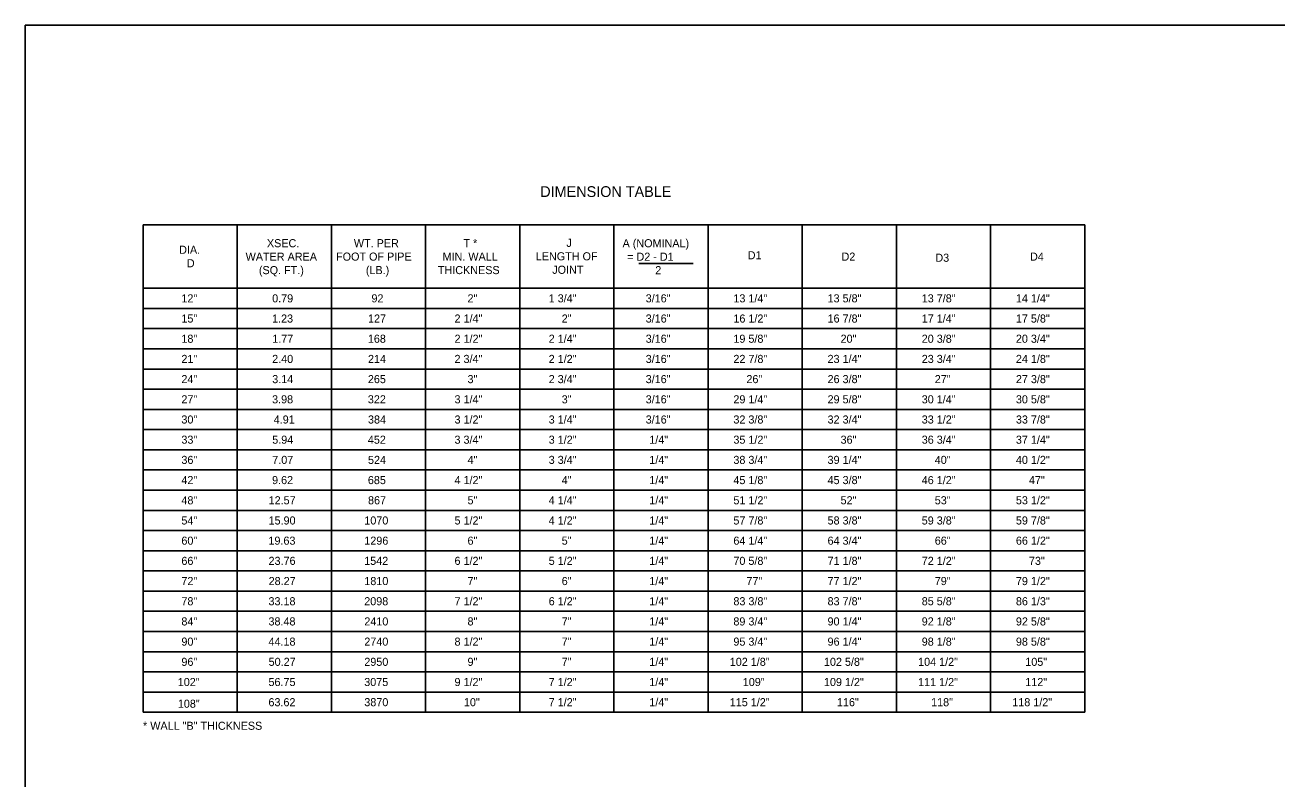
# Model space of a CAD drawing. Extents: x 49991.4 to 50021, y 49987.6 to 50011.4.
# Drawn here: x 49999.38 to 50008.69, y 49993.4 to 49999 of the extents above; entities that cross this region are included whole.
import ezdxf

# ---------------------------------------------------------------- set-up
doc = ezdxf.new("R2010")
doc.units = 0
doc.layers.add('Level 1', color=7, linetype='Continuous')
doc.layers.add('Level 2', color=7, linetype='Continuous')

msp = doc.modelspace()

# ---------------------------------------------------------------- linework, layer by layer
at = {"layer": 'Level 1'}
msp.add_lwpolyline([(49999.3835, 49998.9992), (50016.7501, 49998.9992), (50016.7501, 49987.7988), (49999.3835, 49987.7988)], close=True, dxfattribs=at)
at = {"layer": 'Level 2'}
for p, q in [((50000.2607, 49997.5141), (50000.2607, 49993.8941)), ((50000.2607, 49997.5141), (50007.2607, 49997.5141)), ((50000.9607, 49997.5141), (50000.9607, 49993.8941)), ((50001.6607, 49997.5141), (50001.6607, 49993.8941)), ((50002.3607, 49997.5141), (50002.3607, 49993.8941)), ((50003.0607, 49997.5141), (50003.0607, 49997.0441)), ((50003.7607, 49997.5141), (50003.7607, 49993.8941)), ((50004.4607, 49997.5141), (50004.4607, 49993.8941)), ((50005.1607, 49997.5141), (50005.1607, 49997.0441)), ((50005.8607, 49997.5141), (50005.8607, 49997.0441)), ((50006.5607, 49997.5141), (50006.5607, 49997.0441)), ((50007.2607, 49997.5141), (50007.2607, 49993.8941)), ((50003.945, 49997.2284), (50004.351, 49997.2284)), ((50000.2607, 49997.0441), (50007.2607, 49997.0441)), ((50003.0607, 49997.0428), (50003.0607, 49993.8941)), ((50005.1607, 49997.0441), (50005.1607, 49993.8941)), ((50005.8607, 49997.0441), (50005.8607, 49993.8941)), ((50006.5607, 49997.0402), (50006.5607, 49993.8941)), ((50000.2607, 49996.8941), (50007.2607, 49996.8941)), ((50000.2607, 49996.7441), (50007.2607, 49996.7441)), ((50000.2607, 49996.5941), (50007.2607, 49996.5941)), ((50000.2607, 49996.4441), (50007.2607, 49996.4441)), ((50000.2607, 49996.2941), (50007.2607, 49996.2941)), ((50000.2607, 49996.1441), (50007.2607, 49996.1441)), ((50000.2607, 49995.9941), (50007.2607, 49995.9941)), ((50000.2607, 49995.8441), (50007.2607, 49995.8441)), ((50000.2607, 49995.6941), (50007.2607, 49995.6941)), ((50000.2607, 49995.5441), (50007.2607, 49995.5441)), ((50000.2607, 49995.3941), (50007.2607, 49995.3941)), ((50000.2607, 49995.2441), (50007.2607, 49995.2441)), ((50000.2607, 49995.0941), (50007.2607, 49995.0941)), ((50000.2607, 49994.9441), (50007.2607, 49994.9441)), ((50000.2607, 49994.7941), (50007.2607, 49994.7941)), ((50000.2607, 49994.6441), (50007.2607, 49994.6441)), ((50000.2607, 49994.4941), (50007.2607, 49994.4941)), ((50000.2607, 49994.3441), (50007.2607, 49994.3441)), ((50000.2607, 49994.1941), (50007.2607, 49994.1941)), ((50000.2607, 49994.0441), (50007.2607, 49994.0441)), ((50000.2607, 49993.8941), (50007.2607, 49993.8941))]:
    msp.add_line(p, q, dxfattribs=at)

# ---------------------------------------------------------------- texts
for s, height, p in [('DIMENSION TABLE', 0.08, (50003.2133, 49997.7221)), ('XSEC.', 0.06, (50001.1815, 49997.3487)), ('WT. PER', 0.06, (50001.8278, 49997.3491)), ('T *', 0.06, (50002.6424, 49997.3491)), ('J ', 0.06, (50003.4077, 49997.3514)), (' A (NOMINAL)', 0.06, (50003.8029, 49997.3484)), ('DIA.', 0.06, (50000.529, 49997.2999)), ('WATER AREA', 0.06, (50001.0232, 49997.2487)), ('FOOT OF PIPE', 0.06, (50001.6956, 49997.2491)), ('MIN. WALL', 0.06, (50002.4873, 49997.2491)), ('LENGTH OF', 0.06, (50003.1801, 49997.2514)), ('= D2 - D1', 0.06, (50003.8595, 49997.2484)), ('D1', 0.06, (50004.7555, 49997.2593)), ('D2', 0.06, (50005.4526, 49997.2491)), ('D3', 0.06, (50006.1504, 49997.2407)), ('D4', 0.06, (50006.8538, 49997.2491)), ('D', 0.06, (50000.586, 49997.1999)), ('(SQ. FT.)', 0.06, (50001.1219, 49997.1487)), ('(LB.)', 0.06, (50001.9169, 49997.1491)), ('THICKNESS', 0.06, (50002.4522, 49997.1491)), ('JOINT', 0.06, (50003.3026, 49997.1514)), ('  2 ', 0.06, (50004.0237, 49997.1484)), ('12"', 0.06, (50000.5458, 49996.9391)), ('0.79', 0.06, (50001.2205, 49996.9391)), ('92', 0.06, (50001.9586, 49996.9391)), ('2"', 0.06, (50002.6727, 49996.9391)), ('1 3/4"', 0.06, (50003.276, 49996.9391)), ('3/16"', 0.06, (50003.997, 49996.9391)), ('13 1/4"', 0.06, (50004.649, 49996.9391)), ('13 5/8"', 0.06, (50005.349, 49996.9391)), ('13 7/8"', 0.06, (50006.049, 49996.9391)), ('14 1/4"', 0.06, (50006.749, 49996.9391)), ('15"', 0.06, (50000.5458, 49996.7891)), ('1.23', 0.06, (50001.2198, 49996.7891)), ('127', 0.06, (50001.933, 49996.7891)), ('2 1/4"', 0.06, (50002.5761, 49996.7891)), ('2"', 0.06, (50003.3727, 49996.7891)), ('3/16"', 0.06, (50003.997, 49996.7891)), ('16 1/2"', 0.06, (50004.649, 49996.7891)), ('16 7/8"', 0.06, (50005.349, 49996.7891)), ('17 1/4"', 0.06, (50006.049, 49996.7891)), ('17 5/8"', 0.06, (50006.749, 49996.7891)), ('18"', 0.06, (50000.5458, 49996.6391)), ('1.77', 0.06, (50001.2212, 49996.6391)), ('168', 0.06, (50001.9318, 49996.6391)), ('2 1/2"', 0.06, (50002.5761, 49996.6391)), ('2 1/4"', 0.06, (50003.276, 49996.6391)), ('3/16"', 0.06, (50003.997, 49996.6391)), ('19 5/8"', 0.06, (50004.649, 49996.6391)), ('20"', 0.06, (50005.4458, 49996.6391)), ('20 3/8"', 0.06, (50006.049, 49996.6391)), ('20 3/4"', 0.06, (50006.749, 49996.6391)), ('21"', 0.06, (50000.5458, 49996.4891)), ('2.40', 0.06, (50001.2206, 49996.4891)), ('214', 0.06, (50001.9328, 49996.4891)), ('2 3/4"', 0.06, (50002.576, 49996.4891)), ('2 1/2"', 0.06, (50003.276, 49996.4891)), ('3/16"', 0.06, (50003.997, 49996.4891)), ('22 7/8"', 0.06, (50004.649, 49996.4891)), ('23 1/4"', 0.06, (50005.349, 49996.4891)), ('23 3/4"', 0.06, (50006.049, 49996.4891)), ('24 1/8"', 0.06, (50006.749, 49996.4891)), ('24"', 0.06, (50000.5458, 49996.3391)), ('3.14', 0.06, (50001.221, 49996.3391)), ('265', 0.06, (50001.9319, 49996.3391)), ('3"', 0.06, (50002.6727, 49996.3391)), ('2 3/4"', 0.06, (50003.276, 49996.3391)), ('3/16"', 0.06, (50003.997, 49996.3391)), ('26"', 0.06, (50004.7458, 49996.3391)), ('26 3/8"', 0.06, (50005.349, 49996.3391)), ('27"', 0.06, (50006.1458, 49996.3391)), ('27 3/8"', 0.06, (50006.749, 49996.3391)), ('27"', 0.06, (50000.5458, 49996.1891)), ('3.98', 0.06, (50001.22, 49996.1891)), ('322', 0.06, (50001.9317, 49996.1891)), ('3 1/4"', 0.06, (50002.576, 49996.1891)), ('3"', 0.06, (50003.3727, 49996.1891)), ('3/16"', 0.06, (50003.997, 49996.1891)), ('29 1/4"', 0.06, (50004.649, 49996.1891)), ('29 5/8"', 0.06, (50005.349, 49996.1891)), ('30 1/4"', 0.06, (50006.049, 49996.1891)), ('30 5/8"', 0.06, (50006.749, 49996.1891)), ('30"', 0.06, (50000.5458, 49996.0391)), ('4.91', 0.06, (50001.232, 49996.0391)), ('384', 0.06, (50001.9328, 49996.0391)), ('3 1/2"', 0.06, (50002.576, 49996.0391)), ('3 1/4"', 0.06, (50003.276, 49996.0391)), ('3/16"', 0.06, (50003.997, 49996.0391)), ('32 3/8"', 0.06, (50004.649, 49996.0391)), ('32 3/4"', 0.06, (50005.349, 49996.0391)), ('33 1/2"', 0.06, (50006.049, 49996.0391)), ('33 7/8"', 0.06, (50006.749, 49996.0391)), ('33"', 0.06, (50000.5458, 49995.8891)), ('5.94', 0.06, (50001.221, 49995.8891)), ('452', 0.06, (50001.9317, 49995.8891)), ('3 3/4"', 0.06, (50002.576, 49995.8891)), ('3 1/2"', 0.06, (50003.276, 49995.8891)), ('1/4"', 0.06, (50004.0239, 49995.8891)), ('35 1/2"', 0.06, (50004.649, 49995.8891)), ('36"', 0.06, (50005.4458, 49995.8891)), ('36 3/4"', 0.06, (50006.049, 49995.8891)), ('37 1/4"', 0.06, (50006.749, 49995.8891)), ('36"', 0.06, (50000.5458, 49995.7391)), ('7.07', 0.06, (50001.2212, 49995.7391)), ('524', 0.06, (50001.9328, 49995.7391)), ('4"', 0.06, (50002.6727, 49995.7391)), ('3 3/4"', 0.06, (50003.276, 49995.7391)), ('1/4"', 0.06, (50004.0239, 49995.7391)), ('38 3/4"', 0.06, (50004.649, 49995.7391)), ('39 1/4"', 0.06, (50005.349, 49995.7391)), ('40"', 0.06, (50006.1458, 49995.7391)), ('40 1/2"', 0.06, (50006.749, 49995.7391)), ('42"', 0.06, (50000.5458, 49995.5891)), ('9.62', 0.06, (50001.2198, 49995.5891)), ('685', 0.06, (50001.9319, 49995.5891)), ('4 1/2"', 0.06, (50002.576, 49995.5891)), ('4"', 0.06, (50003.3727, 49995.5891)), ('1/4"', 0.06, (50004.0239, 49995.5891)), ('45 1/8"', 0.06, (50004.649, 49995.5891)), ('45 3/8"', 0.06, (50005.349, 49995.5891)), ('46 1/2"', 0.06, (50006.049, 49995.5891)), ('47"', 0.06, (50006.8458, 49995.5891)), ('48"', 0.06, (50000.5458, 49995.4391)), ('12.57', 0.06, (50001.1942, 49995.4391)), ('867', 0.06, (50001.933, 49995.4391)), ('5"', 0.06, (50002.6727, 49995.4391)), ('4 1/4"', 0.06, (50003.276, 49995.4391)), ('1/4"', 0.06, (50004.0239, 49995.4391)), ('51 1/2"', 0.06, (50004.649, 49995.4391)), ('52"', 0.06, (50005.4458, 49995.4391)), ('53"', 0.06, (50006.1458, 49995.4391)), ('53 1/2"', 0.06, (50006.749, 49995.4391)), ('54"', 0.06, (50000.5458, 49995.2891)), ('15.90', 0.06, (50001.1937, 49995.2891)), ('1070', 0.06, (50001.9055, 49995.2891)), ('5 1/2"', 0.06, (50002.576, 49995.2891)), ('4 1/2"', 0.06, (50003.276, 49995.2891)), ('1/4"', 0.06, (50004.0239, 49995.2891)), ('57 7/8"', 0.06, (50004.649, 49995.2891)), ('58 3/8"', 0.06, (50005.349, 49995.2891)), ('59 3/8"', 0.06, (50006.049, 49995.2891)), ('59 7/8"', 0.06, (50006.749, 49995.2891)), ('60"', 0.06, (50000.5458, 49995.1391)), ('19.63', 0.06, (50001.1928, 49995.1391)), ('1296', 0.06, (50001.9054, 49995.1391)), ('6"', 0.06, (50002.6727, 49995.1391)), ('5"', 0.06, (50003.3727, 49995.1391)), ('1/4"', 0.06, (50004.0239, 49995.1391)), ('64 1/4"', 0.06, (50004.649, 49995.1391)), ('64 3/4"', 0.06, (50005.349, 49995.1391)), ('66"', 0.06, (50006.1458, 49995.1391)), ('66 1/2"', 0.06, (50006.749, 49995.1391)), ('66"', 0.06, (50000.5458, 49994.9891)), ('23.76', 0.06, (50001.1936, 49994.9891)), ('1542', 0.06, (50001.9047, 49994.9891)), ('6 1/2"', 0.06, (50002.576, 49994.9891)), ('5 1/2"', 0.06, (50003.276, 49994.9891)), ('1/4"', 0.06, (50004.0239, 49994.9891)), ('70 5/8"', 0.06, (50004.649, 49994.9891)), ('71 1/8"', 0.06, (50005.349, 49994.9891)), ('72 1/2"', 0.06, (50006.049, 49994.9891)), ('73"', 0.06, (50006.8458, 49994.9891)), ('72"', 0.06, (50000.5458, 49994.8391)), ('28.27', 0.06, (50001.1942, 49994.8391)), ('1810', 0.06, (50001.9055, 49994.8391)), ('7"', 0.06, (50002.6727, 49994.8391)), ('6"', 0.06, (50003.3727, 49994.8391)), ('1/4"', 0.06, (50004.0239, 49994.8391)), ('77"', 0.06, (50004.7458, 49994.8391)), ('77 1/2"', 0.06, (50005.349, 49994.8391)), ('79"', 0.06, (50006.1458, 49994.8391)), ('79 1/2"', 0.06, (50006.7491, 49994.8391)), ('78"', 0.06, (50000.5458, 49994.6891)), ('33.18', 0.06, (50001.1931, 49994.6891)), ('2098', 0.06, (50001.9049, 49994.6891)), ('7 1/2"', 0.06, (50002.576, 49994.6891)), ('6 1/2"', 0.06, (50003.276, 49994.6891)), ('1/4"', 0.06, (50004.0239, 49994.6891)), ('83 3/8"', 0.06, (50004.6491, 49994.6891)), ('83 7/8"', 0.06, (50005.349, 49994.6891)), ('85 5/8"', 0.06, (50006.049, 49994.6891)), ('86 1/3"', 0.06, (50006.749, 49994.6891)), ('84"', 0.06, (50000.5458, 49994.5391)), ('38.48', 0.06, (50001.1931, 49994.5391)), ('2410', 0.06, (50001.9055, 49994.5391)), ('8"', 0.06, (50002.6727, 49994.5391)), ('7"', 0.06, (50003.3727, 49994.5391)), ('1/4"', 0.06, (50004.0239, 49994.5391)), ('89 3/4"', 0.06, (50004.649, 49994.5391)), ('90 1/4"', 0.06, (50005.349, 49994.5391)), ('92 1/8"', 0.06, (50006.049, 49994.5391)), ('92 5/8"', 0.06, (50006.749, 49994.5391)), ('90"', 0.06, (50000.5458, 49994.3891)), ('44.18', 0.06, (50001.1931, 49994.3891)), ('2740', 0.06, (50001.9055, 49994.3891)), ('8 1/2"', 0.06, (50002.576, 49994.3891)), ('7"', 0.06, (50003.3727, 49994.3891)), ('1/4"', 0.06, (50004.0239, 49994.3891)), ('95 3/4"', 0.06, (50004.649, 49994.3891)), ('96 1/4"', 0.06, (50005.349, 49994.3891)), ('98 1/8"', 0.06, (50006.049, 49994.3891)), ('98 5/8"', 0.06, (50006.749, 49994.3891)), ('96"', 0.06, (50000.5458, 49994.2391)), ('50.27', 0.06, (50001.1942, 49994.2391)), ('2950', 0.06, (50001.9055, 49994.2391)), ('9"', 0.06, (50002.6727, 49994.2391)), ('7"', 0.06, (50003.3727, 49994.2391)), ('1/4"', 0.06, (50004.0239, 49994.2391)), ('102 1/8"', 0.06, (50004.6221, 49994.2391)), ('102 5/8"', 0.06, (50005.3221, 49994.2391)), ('104 1/2"', 0.06, (50006.0221, 49994.2391)), ('105"', 0.06, (50006.8188, 49994.2391)), ('102"', 0.06, (50000.5188, 49994.0891)), ('56.75', 0.06, (50001.1931, 49994.0891)), ('3075', 0.06, (50001.905, 49994.0891)), ('9 1/2"', 0.06, (50002.576, 49994.0891)), ('7 1/2"', 0.06, (50003.276, 49994.0891)), ('1/4"', 0.06, (50004.0239, 49994.0891)), ('109"', 0.06, (50004.7188, 49994.0891)), ('109 1/2"', 0.06, (50005.3221, 49994.0891)), ('111 1/2"', 0.06, (50006.0221, 49994.0891)), ('112"', 0.06, (50006.8188, 49994.0891)), ('108"', 0.06, (50000.5193, 49993.9279)), ('63.62', 0.06, (50001.1929, 49993.9391)), ('3870', 0.06, (50001.9055, 49993.9391)), ('10"', 0.06, (50002.6458, 49993.9391)), ('7 1/2"', 0.06, (50003.276, 49993.9391)), ('1/4"', 0.06, (50004.0239, 49993.9391)), ('115 1/2"', 0.06, (50004.6221, 49993.9391)), ('116"', 0.06, (50005.4188, 49993.9391)), ('118"', 0.06, (50006.1188, 49993.9391)), ('118 1/2"', 0.06, (50006.7221, 49993.9391)), ('* WALL "B" THICKNESS', 0.06, (50000.2607, 49993.7641))]:
    msp.add_text(s, height=height, dxfattribs=at).set_placement(p)

doc.saveas('drawing.dxf')
